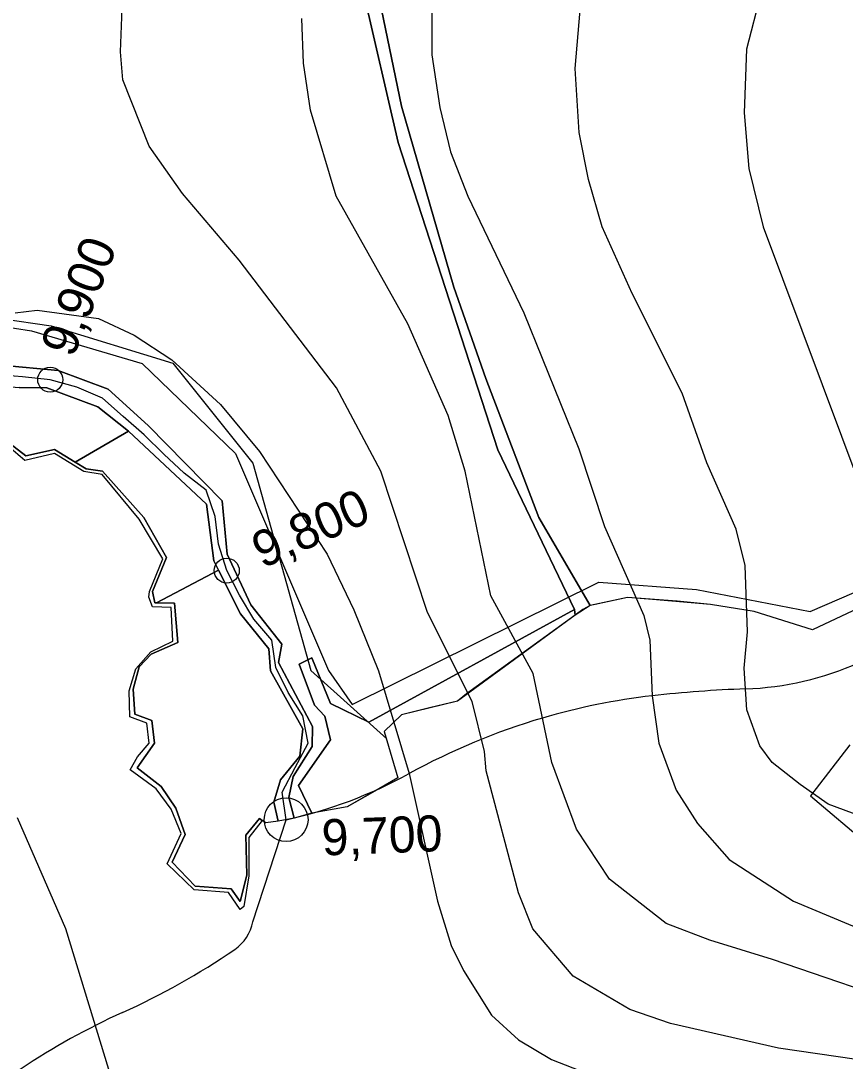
# Model space of a CAD drawing. Extents: x -510989 to -501240, y -1184665 to -1176089.
# Drawn here: x -509339.7 to -509042.8, y -1180893.6 to -1180518.8 of the extents above; entities that cross this region are included whole.
import ezdxf

# ---------------------------------------------------------------- set-up
doc = ezdxf.new("R2010")
doc.units = 0
for name, color, linetype in [('NAVRH_revitalizace_toku', 7, 'Continuous'), ('NAVRH_rozvodnice', 7, 'Continuous'), ('ostatni_plocha_x_neplodna_puda', 7, 'Continuous'), ('ostatni_plocha_x_ostatni_komunikace', 7, 'Continuous'), ('popis', 7, 'Continuous'), ('STAV_povodi', 7, 'Continuous'), ('STAV_systematicke_odvodneni', 7, 'Continuous'), ('STAV_USES', 7, 'Continuous'), ('trasovani_toku', 7, 'Continuous'), ('trvaly_travni_porost', 7, 'Continuous'), ('vodni_plocha_x_vodni_tok_v_koryt_prir_n_upr', 7, 'Continuous'), ('vodni_plocha_x_vodni_tok_v_koryte_umelem', 7, 'Continuous'), ('vrstevnice_01', 7, 'Continuous'), ('vrstevnice_02', 7, 'Continuous')]:
    doc.layers.add(name, color=color, linetype=linetype)

msp = doc.modelspace()

# ---------------------------------------------------------------- linework, layer by layer
at = {"layer": 'NAVRH_revitalizace_toku'}
msp.add_lwpolyline([(-509217.43, -1180056.92), (-509232.5, -1180170.63), (-509254.42, -1180314.47), (-509261.27, -1180377.49), (-509279.08, -1180419.96), (-509306.48, -1180458.32), (-509365.38, -1180499.42), (-509395.55, -1180530.26), (-509400.81, -1180563.08), (-509388.25, -1180600.36), (-509365.16, -1180623.45), (-509328.69, -1180628.72), (-509284.94, -1180642.09), (-509256.17, -1180678.15), (-509235.24, -1180752.86), (-509207.84, -1180777.52)], dxfattribs=at)
at = {"layer": 'NAVRH_rozvodnice'}
msp.add_line((-509256.12, -1180843.38), (-509244.13, -1180806.63), dxfattribs=at)
for centre, radius, start, end in [((-509082.69, -1180649.61), 109.97, 272.0844, 294.0839), ((-509086.64, -1180990.12), 229.56, 96.4197, 106.4877), ((-509062.47, -1181204.93), 445.73, 92.0844, 96.4197), ((-509082.63, -1181003.7), 243.72, 106.4877, 118.7389), ((-509279.88, -1180643.98), 166.53, 282.3976, 298.7389), ((-509271.49, -1180840.48), 15.64, 304.362, 349.303), ((-509412.14, -1180634.76), 264.85, 294.3222, 304.362), ((-509199.37, -1181105.52), 251.76, 114.3222, 133.3684)]:
    msp.add_arc(centre, radius, start, end, dxfattribs=at)
at = {"layer": 'ostatni_plocha_x_neplodna_puda'}
for points in [[(-509345.91, -1180650.45), (-509340.3, -1180650.85), (-509330.29, -1180650.97), (-509311.95, -1180657.91), (-509300.87, -1180666.66), (-509320.07, -1180677.79), (-509327.53, -1180673.19), (-509337.82, -1180675.47), (-509347.98, -1180667.81), (-509361.09, -1180668.74), (-509369.02, -1180671.6), (-509379.27, -1180668.49)], [(-509300.87, -1180666.66), (-509272.8, -1180692.91), (-509270.17, -1180713.31), (-509268.47, -1180716.7), (-509290.76, -1180728.46), (-509291.44, -1180728.45), (-509292.21, -1180724.39), (-509287.17, -1180712.17), (-509295.34, -1180697.76), (-509310.27, -1180681.11), (-509316.13, -1180680.22), (-509320.07, -1180677.79)], [(-509290.76, -1180728.46), (-509268.47, -1180716.7), (-509260.57, -1180732.43), (-509250.32, -1180745.02), (-509249.72, -1180753.04), (-509238.13, -1180773.85), (-509239.24, -1180783.77), (-509246.12, -1180792.31), (-509248.61, -1180800.3), (-509247.02, -1180807.21), (-509251.46, -1180807.75), (-509252.71, -1180806.92), (-509253.72, -1180806.25), (-509258.62, -1180812.2), (-509258.32, -1180826.58), (-509260.73, -1180836.05), (-509263.94, -1180831.54), (-509276.86, -1180830.54), (-509285.19, -1180821.89), (-509280.47, -1180811.99), (-509283.84, -1180802.46), (-509289.07, -1180794.71), (-509297.79, -1180787.91), (-509291.58, -1180779.1), (-509292.5, -1180770.84), (-509298.57, -1180768.65), (-509299.18, -1180759.64), (-509297.06, -1180751.6), (-509292.73, -1180747), (-509283.17, -1180742.76), (-509284.27, -1180728.57)]]:
    msp.add_lwpolyline(points, close=True, dxfattribs=at)
at = {"layer": 'ostatni_plocha_x_ostatni_komunikace'}
msp.add_lwpolyline([(-509210.56, -1180511.17), (-509202.62, -1180549.54), (-509183.7, -1180614.73), (-509172.2, -1180647.68), (-509153.11, -1180697.78), (-509134.71, -1180729.45), (-509137.29, -1180730.91), (-509140.08, -1180732.93), (-509140.35, -1180730.93), (-509167.86, -1180673.36), (-509185.27, -1180619.72), (-509203.81, -1180562.6), (-509216.38, -1180507.98)], dxfattribs=at)
at = {"layer": 'popis'}
msp.add_lwpolyline([(-509035.95, -1180729.49), (-509054.57, -1180738.26), (-509075.64, -1180731.65), (-509091.36, -1180729.12), (-509112.24, -1180727.24), (-509121.19, -1180726.62), (-509134.71, -1180729.45), (-509140.08, -1180732.93), (-509182.37, -1180763.88), (-509192.48, -1180766.33), (-509202.6, -1180768.79), (-509208.87, -1180774.82), (-509203.96, -1180791.59), (-509213.07, -1180796.79), (-509222.17, -1180802), (-509234.89, -1180804.32), (-509241.24, -1180806.05), (-509247.02, -1180807.21), (-509251.46, -1180807.75), (-509252.71, -1180806.92), (-509257.56, -1180813.02), (-509257.56, -1180826.87), (-509259.36, -1180837.96), (-509260.74, -1180838.93), (-509264.89, -1180832.82), (-509277.22, -1180831.85), (-509286.91, -1180822.57), (-509281.92, -1180811.63), (-509285.51, -1180802.79), (-509290.91, -1180795.45), (-509300.32, -1180788.66), (-509297.69, -1180783.95), (-509293.39, -1180779.11), (-509294.34, -1180771.81), (-509300.43, -1180769.6), (-509300.71, -1180760.18), (-509298.22, -1180752.29), (-509292.82, -1180746.19), (-509284.92, -1180742.3), (-509285.48, -1180730.18), (-509292.26, -1180729.9), (-509293.51, -1180726.44), (-509293.37, -1180724.36), (-509288.52, -1180712.59), (-509297.1, -1180698.36), (-509310.38, -1180682.29), (-509316.98, -1180681.23), (-509327.5, -1180674.72), (-509338.16, -1180677.21), (-509347.57, -1180669.32)], dxfattribs=at)
at = {"layer": 'STAV_povodi'}
msp.add_line((-509256.12, -1180843.38), (-509244.13, -1180806.63), dxfattribs=at)
for centre, radius, start, end in [((-509082.69, -1180649.61), 109.97, 272.0844, 294.0839), ((-509086.64, -1180990.12), 229.56, 96.4197, 106.4877), ((-509062.47, -1181204.93), 445.73, 92.0844, 96.4197), ((-509082.63, -1181003.7), 243.72, 106.4877, 118.7389), ((-509279.88, -1180643.98), 166.53, 282.3976, 298.7389), ((-509271.49, -1180840.48), 15.64, 304.362, 349.303), ((-509412.14, -1180634.76), 264.85, 294.3222, 304.362), ((-509199.37, -1181105.52), 251.76, 114.3222, 133.3684)]:
    msp.add_arc(centre, radius, start, end, dxfattribs=at)
at = {"layer": 'STAV_systematicke_odvodneni'}
for p, q in [((-509368.79, -1180625.19), (-509335.81, -1180630.51)), ((-509335.81, -1180630.51), (-509295.91, -1180642.22)), ((-509295.91, -1180642.22), (-509262.4, -1180674.69)), ((-509262.4, -1180674.69), (-509228.88, -1180752.92)), ((-509055.46, -1180731.63), (-508981.51, -1180699.7)), ((-509220.37, -1180765.16), (-509131.53, -1180720.99)), ((-509131.53, -1180720.99), (-509096.42, -1180723.65)), ((-509096.42, -1180723.65), (-509055.46, -1180731.63)), ((-509228.88, -1180752.92), (-509220.37, -1180765.16))]:
    msp.add_line(p, q, dxfattribs=at)
at = {"layer": 'STAV_USES'}
for p, q in [((-509041.1, -1180779.62), (-509055.36, -1180798.02)), ((-509041.1, -1180779.62), (-509055.36, -1180798.02)), ((-509055.36, -1180798.02), (-508878.36, -1180948.26)), ((-509055.36, -1180798.02), (-508878.36, -1180948.26))]:
    msp.add_line(p, q, dxfattribs=at)
at = {"layer": 'trasovani_toku'}
for p, q in [((-509339.04, -1180647.05), (-509349.01, -1180646.27)), ((-509329.09, -1180648.09), (-509339.04, -1180647.05)), ((-509319.48, -1180650.84), (-509329.09, -1180648.09)), ((-509310.26, -1180654.73), (-509319.48, -1180650.84)), ((-509302.81, -1180661.39), (-509310.26, -1180654.73)), ((-509295.23, -1180667.91), (-509302.81, -1180661.39)), ((-509288.12, -1180674.95), (-509295.23, -1180667.91)), ((-509280.82, -1180681.78), (-509288.12, -1180674.95)), ((-509272.95, -1180687.95), (-509280.82, -1180681.78)), ((-509269.64, -1180697.39), (-509272.95, -1180687.95)), ((-509268.47, -1180707.32), (-509269.64, -1180697.39)), ((-509265.51, -1180716.87), (-509268.47, -1180707.32)), ((-509260.94, -1180725.77), (-509265.51, -1180716.87)), ((-509255.78, -1180734.33), (-509260.94, -1180725.77)), ((-509249.23, -1180741.89), (-509255.78, -1180734.33)), ((-509247.85, -1180751.79), (-509249.23, -1180741.89)), ((-509243.4, -1180760.75), (-509247.85, -1180751.79)), ((-509238.09, -1180769.22), (-509243.4, -1180760.75)), ((-509236.22, -1180779.04), (-509238.09, -1180769.22)), ((-509240.93, -1180787.87), (-509236.22, -1180779.04)), ((-509245.56, -1180796.73), (-509240.93, -1180787.87)), ((-509244.13, -1180806.63), (-509245.56, -1180796.73))]:
    msp.add_line(p, q, dxfattribs=at)
for centre, radius in [((-509329.09, -1180648.09), 4.5), ((-509265.51, -1180716.87), 4.5), ((-509244.13, -1180806.63), 7.88)]:
    msp.add_circle(centre, radius, dxfattribs=at)
at = {"layer": 'trvaly_travni_porost'}
for points in [[(-509216.38, -1180507.98), (-509203.81, -1180562.6), (-509185.27, -1180619.72), (-509167.86, -1180673.36), (-509140.35, -1180730.93), (-509214.4, -1180771.48), (-509228.21, -1180764.77), (-509234.93, -1180748.26), (-509239.46, -1180750.61), (-509233.93, -1180765.31), (-509230.16, -1180769.27), (-509228.17, -1180777.8), (-509239.65, -1180794.32), (-509234.89, -1180804.32), (-509241.24, -1180806.05), (-509243.2, -1180798.6), (-509241.61, -1180791.06), (-509234.76, -1180780.22), (-509234.62, -1180773.1), (-509246.86, -1180750.03), (-509245.73, -1180743.36), (-509256.87, -1180729.16), (-509265.37, -1180710.96), (-509267.2, -1180691.77), (-509293.77, -1180664.65), (-509308.22, -1180651.52), (-509326.27, -1180644.8), (-509346.73, -1180642.81)], [(-509035.95, -1180729.49), (-509054.57, -1180738.26), (-509075.64, -1180731.65), (-509091.36, -1180729.12), (-509103.3, -1180727.86), (-509121.19, -1180726.62), (-509132.83, -1180729.06), (-509134.71, -1180729.45), (-509153.11, -1180697.78), (-509172.2, -1180647.68), (-509183.7, -1180614.73), (-509202.62, -1180549.54), (-509210.56, -1180511.17)]]:
    msp.add_lwpolyline(points, dxfattribs=at)
msp.add_lwpolyline([(-509140.35, -1180730.93), (-509140.08, -1180732.93), (-509179.19, -1180761.28), (-509182.37, -1180763.88), (-509202.6, -1180768.79), (-509208.87, -1180774.82), (-509203.96, -1180791.59), (-509222.17, -1180802), (-509234.89, -1180804.32), (-509239.65, -1180794.32), (-509228.17, -1180777.8), (-509230.16, -1180769.27), (-509233.93, -1180765.31), (-509239.46, -1180750.61), (-509234.93, -1180748.26), (-509228.21, -1180764.77), (-509214.4, -1180771.48)], close=True, dxfattribs=at)
at = {"layer": 'vodni_plocha_x_vodni_tok_v_koryt_prir_n_upr'}
msp.add_lwpolyline([(-509347.98, -1180667.81), (-509337.82, -1180675.47), (-509327.53, -1180673.19), (-509320.07, -1180677.79), (-509316.13, -1180680.22), (-509310.27, -1180681.11), (-509295.34, -1180697.76), (-509287.17, -1180712.17), (-509292.21, -1180724.39), (-509291.44, -1180728.45), (-509290.76, -1180728.46), (-509284.27, -1180728.57), (-509283.17, -1180742.76), (-509292.73, -1180747), (-509297.06, -1180751.6), (-509299.18, -1180759.64), (-509298.57, -1180768.65), (-509292.5, -1180770.84), (-509291.58, -1180779.1), (-509297.79, -1180787.91), (-509289.07, -1180794.71), (-509283.84, -1180802.46), (-509280.47, -1180811.99), (-509285.19, -1180821.89), (-509276.86, -1180830.54), (-509263.94, -1180831.54), (-509260.73, -1180836.05), (-509258.32, -1180826.58), (-509258.62, -1180812.2), (-509253.72, -1180806.25), (-509252.71, -1180806.92), (-509257.56, -1180813.02), (-509257.56, -1180826.87), (-509259.36, -1180837.96), (-509260.74, -1180838.93), (-509264.89, -1180832.82), (-509277.22, -1180831.85), (-509286.91, -1180822.57), (-509281.92, -1180811.63), (-509285.51, -1180802.79), (-509290.91, -1180795.45), (-509300.32, -1180788.66), (-509297.69, -1180783.95), (-509293.39, -1180779.11), (-509294.34, -1180771.81), (-509300.43, -1180769.6), (-509300.71, -1180760.18), (-509298.22, -1180752.29), (-509292.82, -1180746.19), (-509284.92, -1180742.3), (-509285.48, -1180730.18), (-509292.26, -1180729.9), (-509293.51, -1180726.44), (-509293.37, -1180724.36), (-509288.52, -1180712.59), (-509297.1, -1180698.36), (-509310.38, -1180682.29), (-509316.98, -1180681.23), (-509327.5, -1180674.72), (-509338.16, -1180677.21), (-509347.57, -1180669.32)], dxfattribs=at)
at = {"layer": 'vodni_plocha_x_vodni_tok_v_koryte_umelem'}
msp.add_lwpolyline([(-509346.73, -1180642.81), (-509326.27, -1180644.8), (-509308.22, -1180651.52), (-509293.77, -1180664.65), (-509267.2, -1180691.77), (-509265.37, -1180710.96), (-509256.87, -1180729.16), (-509245.73, -1180743.36), (-509246.86, -1180750.03), (-509234.62, -1180773.1), (-509234.76, -1180780.22), (-509241.61, -1180791.06), (-509243.2, -1180798.6), (-509241.24, -1180806.05), (-509247.02, -1180807.21), (-509248.61, -1180800.3), (-509246.12, -1180792.31), (-509239.24, -1180783.77), (-509238.13, -1180773.85), (-509249.72, -1180753.04), (-509250.32, -1180745.02), (-509260.57, -1180732.43), (-509268.47, -1180716.7), (-509270.17, -1180713.31), (-509272.8, -1180692.91), (-509300.87, -1180666.66), (-509311.95, -1180657.91), (-509330.29, -1180650.97), (-509340.3, -1180650.85)], dxfattribs=at)
at = {"layer": 'vrstevnice_01'}
for points in [[(-509016.31, -1180875), (-509069, -1180857), (-509091.59, -1180850), (-509107.31, -1180844), (-509127.69, -1180828), (-509139.59, -1180810), (-509148.41, -1180786), (-509155.19, -1180754), (-509170.41, -1180726), (-509179.69, -1180681), (-509185.81, -1180661), (-509200.31, -1180628), (-509226.09, -1180582), (-509235.41, -1180551), (-509237.91, -1180534), (-509238.5, -1180518)], [(-508952, -1180837), (-509049, -1180801), (-509059.09, -1180794), (-509069.09, -1180786), (-509073.59, -1180780), (-509078.19, -1180767), (-509079.19, -1180752), (-509078, -1180739), (-509078.81, -1180715), (-509082.09, -1180702), (-509092.69, -1180678), (-509101.5, -1180653), (-509119.5, -1180617), (-509130.31, -1180593), (-509135.31, -1180576), (-509138.59, -1180559), (-509140, -1180536), (-509138.31, -1180515)], [(-509341.69, -1180624), (-509333.81, -1180623), (-509311.69, -1180626), (-509298.81, -1180632), (-509285.31, -1180641), (-509267.81, -1180657), (-509253.69, -1180674), (-509229.41, -1180711), (-509219.81, -1180731), (-509210.91, -1180753), (-509199.81, -1180790), (-509189.59, -1180836), (-509184.69, -1180852), (-509180.31, -1180861), (-509170.19, -1180877), (-509160.41, -1180886), (-509148.59, -1180893), (-509125.5, -1180902)], [(-509306.69, -1180901), (-509323.41, -1180846), (-509340.81, -1180806)]]:
    msp.add_lwpolyline(points, dxfattribs=at)
at = {"layer": 'vrstevnice_02'}
for points in [[(-509019.31, -1180478), (-509045.5, -1180485), (-509055, -1180489), (-509060.69, -1180493), (-509070.19, -1180504), (-509073.19, -1180509), (-509078.31, -1180529), (-509079.19, -1180552), (-509077.5, -1180572), (-509072.31, -1180593), (-509037.19, -1180687)], [(-509191.69, -1180498), (-509191.69, -1180531), (-509188.81, -1180550), (-509185, -1180566), (-509178.69, -1180582), (-509158.59, -1180624), (-509138.69, -1180673), (-509129.5, -1180701), (-509115.31, -1180733)], [(-509038.81, -1180893), (-509066.81, -1180889), (-509105.69, -1180880), (-509120.41, -1180875), (-509140.81, -1180863), (-509155.31, -1180846), (-509160.5, -1180833), (-509172.09, -1180789), (-509172.69, -1180782), (-509177.09, -1180764), (-509193.19, -1180732), (-509210, -1180681), (-509226, -1180651), (-509261, -1180605), (-509281.41, -1180581), (-509293.41, -1180564), (-509302.91, -1180540), (-509303.81, -1180530), (-509302.91, -1180508)], [(-509115.31, -1180733), (-509113.19, -1180742), (-509112.31, -1180762), (-509109.91, -1180779), (-509103.69, -1180796), (-509096, -1180808), (-509084.59, -1180821), (-509061.41, -1180836), (-509035, -1180847)]]:
    msp.add_lwpolyline(points, dxfattribs=at)

# ---------------------------------------------------------------- texts
at = {"layer": 'trasovani_toku'}
for s, rotation, p in [('9,900', 68.4243, (-509320.84, -1180640.56)), ('9,800', 23.5959, (-509252.71, -1180716.24)), ('9,700', 2.185, (-509231.09, -1180819.56))]:
    msp.add_text(s, height=13, rotation=rotation, dxfattribs=at).set_placement(p)

doc.saveas('drawing.dxf')
